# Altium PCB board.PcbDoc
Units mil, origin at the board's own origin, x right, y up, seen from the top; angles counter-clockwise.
Board outline 2598.43 x 1240.16 mil, 2 copper layers (Top Layer, Bottom Layer); 40 components, 36 nets, 194 pads, 31 vias.
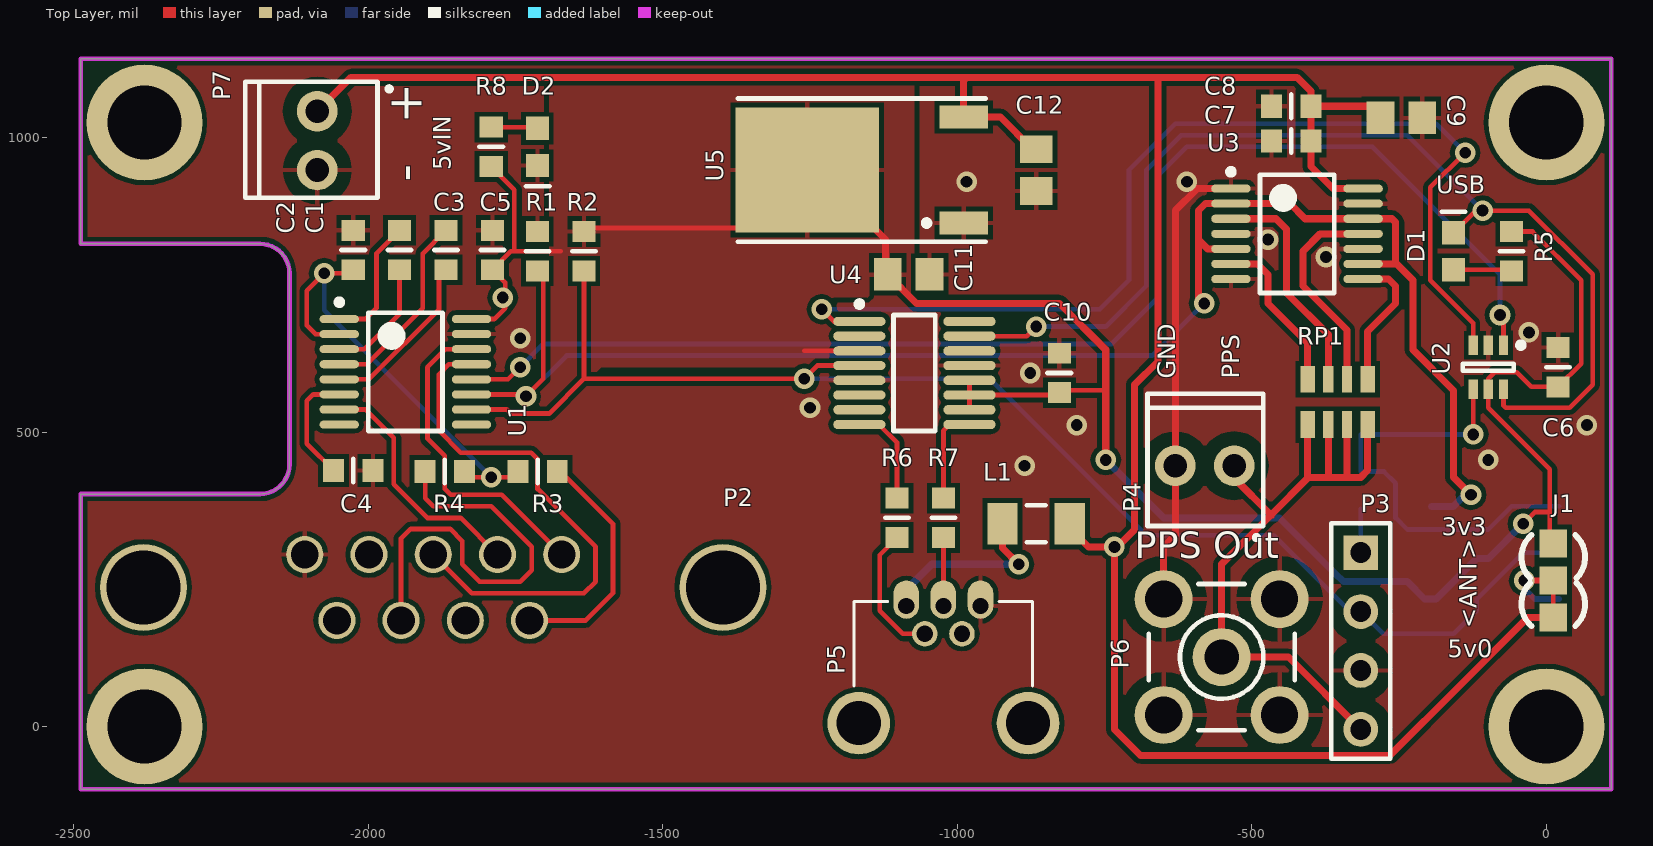
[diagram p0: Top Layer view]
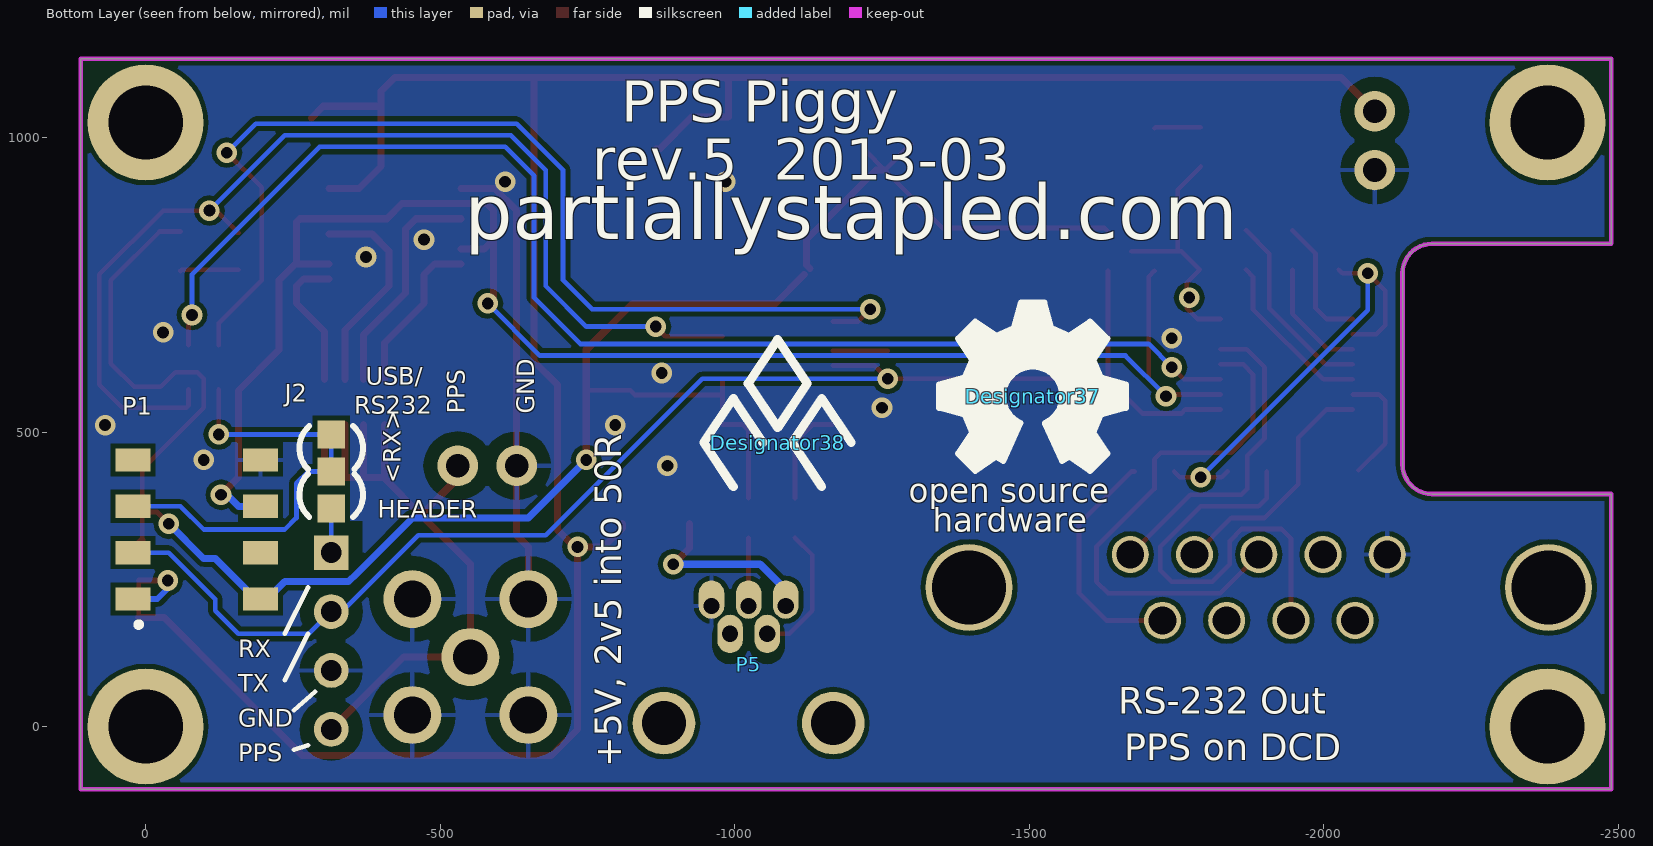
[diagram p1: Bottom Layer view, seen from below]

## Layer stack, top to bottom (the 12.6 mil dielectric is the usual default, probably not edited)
Top Layer: signal copper 1.4
Dielectric: dielectric 12.6, FR-4, Dk 4.8
Bottom Layer: signal copper 1.4

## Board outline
-2488.19,-106.3 -2488.19,394.88 -2183.86,394.88 ccw(c-2183.86,444.88) -2133.86,444.88 -2133.86,769.69 ccw(c-2183.86,769.69) -2183.86,819.69 -2488.19,819.69 -2488.19,1133.86 110.24,1133.86 110.24,-106.3

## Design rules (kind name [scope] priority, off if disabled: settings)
Clearance FarFill [InPolygon vs InComponentClass('FarFill')] p1: gap=23.62
Clearance [All] p2: gap=8
Height [All] p1: minheight=0 maxheight=10000 prefheight=500
HoleSize [All] p1: absolutevalues=TRUE maxlimit=250 minlimit=13 maxpercent=80.000 minpercent=20.000
MinimumAnnularRing [All] p1: minimumring=7
MinimumSolderMaskSliver [All] p1: minsoldermaskwidth=0
NetAntennae jumpers [InNet('VANT') or InNet('RX')] p1: netantennaetolerance=1000
NetAntennae [All] p2: netantennaetolerance=0
PasteMaskExpansion NoPaste [InComponent('U1') or InComponent('U3') or InComponent('U4')] p1: expansion=-100
PasteMaskExpansion [All] p2: expansion=0
PolygonConnect "Direct Vias" [IsVia] p1: connectstyle=Direct reliefconductorwidth=10 reliefentries=4 polygonreliefangle="90 Angle"
PolygonConnect [All] p2: connectstyle=Relief reliefconductorwidth=8 reliefentries=4 polygonreliefangle="90 Angle"
RoutingVias [All] p1: holewidth=20 width=35 viastyle="Through Hole" minholewidth=20 minwidth=35 maxholewidth=20 maxwidth=35
ShortCircuit jumper_rx [InNet('RX') vs InNet('RX_AB')] p1: allowed=TRUE
ShortCircuit jumper_vant [InNet('+5') vs InNet('VANT')] p2: allowed=TRUE
ShortCircuit [All] p3: allowed=FALSE
SilkToSilkClearance [All] p1: silktosilkclearance=1
SilkscreenOverComponentPads [All] p1: minsilkscreentomaskgap=1
SolderMaskExpansion "tent vias" [isvia and (not innet('+3.3') and not innet('gnd'))] p1: expansion=-999
SolderMaskExpansion [All] p2: expansion=4
Width [All] p1: maxlimit=12 minlimit=8 preferedwidth=8
20 further rules are at their usual default settings.

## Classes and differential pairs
component class FarFill: P3 P4 P6 P7

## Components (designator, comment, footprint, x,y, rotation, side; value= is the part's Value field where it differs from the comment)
C1 "100n" RESC1608N -1946.85,809.06 r270 top
C2 "100n" RESC1608N -2025.59,809.06 r270 top
C3 "100n" RESC1608N -1868.11,809.06 r90 top
C4 "100n" RESC1608N -2025.59,435.04 r180 top
C5 "100n" RESC1608N -1789.37,809.06 r270 top
C6 "100n" RESC1608N 19.68,610.24 r270 top
C7 "10n" RESC1608N -433.07,994.09 r0 top
C8 "100n" RESC1608N -433.07,1053.15 r0 top
C9 "10u" RESC2012N -246.06,1033.46 r180 top
C10 "100n" RESC1608N -826.77,600.39 r270 top
C11 "4.7u" RESC2012N -1082.68,767.72 r180 top
C12 "4.7u" RESC2012N -866.14,944.88 r90 top
D1 "GRN" DIO1608N -157.48,807.09 r90 top
D2 "GRN" DIO1608N -1712.6,984.25 r270 top
Designator37 "Comment" OSHW_300 -1505.91,561.02 r180 bottom
Designator38 "Comment" ARMS_250 -1072.83,482.28 r180 bottom
J1 "Solder Jumper" SOL_JUMP_3 11.81,248.03 r270 top
J2 "Solder Jumper" sol_jump_3 -314.96,433.07 r90 bottom
L1 "HI1206T500R-10" RESC3216N -866.14,344.49 r0 top
P1 "To Trimble Board" NPPN042FFKS-RC_REV -47.24,216.54 r90 bottom
P2 "DE-9 Female" DE9_1734348 -1889.76,236.22 r0 top
P3 "Header 4" HDR1X4 -314.96,295.28 r270 top
P4 "640454-2" TEC_640454-2 -629.92,442.91 r0 top
P5 "USB" 0548190519 -1023.62,157.48 r90 top
P6 "SMA" SMA_COAX -551.18,118.11 r0 top
P7 "640454-2" TEC_640454-2 -2086.61,944.88 r90 top
R1 "10K" RESC1608N -1712.6,807.09 r270 top
R2 "10K" RESC1608N -1633.86,807.09 r270 top
R3 "270" RESC1608N -1712.6,433.07 r180 top
R4 "270" RESC1608N -1870.08,433.07 r0 top
R5 "270" RESC1608N -59.06,807.09 r90 top
R6 "22" RESC1608N -1102.36,354.33 r90 top
R7 "22" RESC1608N -1023.62,354.33 r90 top
R8 "270" RESC1608N -1791.34,984.25 r270 top
RP1 "120" CRA06S -354.33,551.18 r0 top
U1 "ST3232CTR" TSSOP16_N -1937.01,602.36 r0 top
U2 "74LVC1G157GW" SOT363-6N -98.43,610.24 r270 top
U3 "SN74ABT125PWLE" PW014_N -423.23,836.61 r0 top
U4 "FT230XS-R" SOP635P600-16N -1072.83,600.39 r0 top
U5 "AP1117D" TO-252 -1122.05,944.88 r90 top

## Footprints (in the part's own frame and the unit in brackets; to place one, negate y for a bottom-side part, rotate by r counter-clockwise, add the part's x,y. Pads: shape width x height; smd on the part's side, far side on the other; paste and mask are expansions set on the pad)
0548190519 [mm] "CONN USB RECEPTACLE 5POS RT ANG"
  round 2.7 hole 1.9: 0(-3.85,-3.65) 0(-3.85,3.65)
  oval 1.65x1.1 hole 0.7 copper offset 0.275,0: 1(1.2,1.6) 3(1.2,0) 5(1.2,-1.6)
  round 1.1 hole 0.7: 2(0,0.8) 4(0,-0.8)
  oval 1.65x1.1 smd far side: 2(0,0.8) 4(0,-0.8)
  silkscreen extent -2.25,-3.85 1.4,3.85, body extent -7.6,-3.85 1.4,3.85, height 3.95
ARMS_250 [mil]
  silkscreen extent -125,-75 125,175
CRA06S [mm]
  rect 0.63x1.15 smd paste-0.05 mask+0: 1(-1.295,0.975) 4(1.295,0.975) 5(1.295,-0.975) 8(-1.295,-0.975)
  rect 0.44x1.15 smd mask+0: 2(-0.4,0.975) 3(0.4,0.975) 6(0.4,-0.975) 7(-0.4,-0.975)
  body extent -1.6,-0.8 1.6,0.8, height 0.5
DE9_1734348 [mm]
  round 3.75 hole 3.2: 0(-12.495,0) 0(12.495,0)
  round 1.6 hole 1.2: 1(5.54,1.42) 2(2.77,1.42) 3(0,1.42) 4(-2.77,1.42) 5(-5.54,1.42) 6(4.155,-1.42) 7(1.385,-1.42) 8(-1.385,-1.42) 9(-4.155,-1.42)
  body extent -15,-9.5 15,3, height 12.5
DIO1608N [mm] "Chip LED, Body 1.6x0.8mm, IPC Medium Density"
  rect 1x1 smd: 1(-0.8,0) 2(0.8,0)
  silkscreen extent 1.7,-0.5 1.7,0.52, body extent -0.87,-0.48 0.87,0.48, height 0.85
HDR1X4 [mm] "Connector; Header; 4 Position"
  rect 1.5x1.5 hole 0.9: 1(0,0)
  round 1.5 hole 0.9: 2(2.54,0) 3(5.08,0) 4(7.62,0)
  silkscreen extent -1.27,-1.27 8.89,1.27
NPPN042FFKS-RC_REV [mm] "2mm header receptacle with bottom entry"
  rect 1x1.5 smd: 1(0,1.75) 2(0,-3.75) 3(2,1.75) 4(2,-3.75) 5(4,1.75) 6(4,-3.75) 7(6,1.75) 8(6,-3.75)
  silkscreen extent -1.2,1.4 -1,1.6, body extent -1,-3 7,1, height 4.4
OSHW_300 [mil]
  silkscreen extent -159,-127 159,159
PW014_N [mm] "TSOP, 14-Leads, Body 5x4.4mm, Pitch 0.65mm, IPC Medium Density"
  oval 1.7x0.35 smd: 1(-2.85,1.95) 2(-2.85,1.3) 3(-2.85,0.65) 4(-2.85,0) 5(-2.85,-0.65) 6(-2.85,-1.3) 7(-2.85,-1.95) 8(2.85,-1.95) 9(2.85,-1.3) 10(2.85,-0.65) 11(2.85,0) 12(2.85,0.65) 13(2.85,1.3) 14(2.85,1.95)
  silkscreen extent -2.97,-2.55 1.6,2.8, body extent -2.25,-2.55 2.25,2.55, height 1.2
RESC1608N [mm] "Chip Resistor, Body 1.6x0.8mm, IPC Medium Density"
  rect 0.9x1 smd: 1(-0.85,0) 2(0.85,0)
  silkscreen extent 0,-0.51 0,0.51, body extent -0.85,-0.48 0.85,0.48, height 0.6
RESC2012N [mm] "Chip Resistor, Body 2.0x1.3mm, IPC Medium Density"
  rect 1.2x1.4 smd: 1(-0.9,0) 2(0.9,0)
  body extent -1.07,-0.7 1.07,0.7, height 0.65
RESC3216N [mm] "Chip Resistor, Body 3.2x1.6mm, IPC Medium Density"
  rect 1.3x1.8 smd: 1(-1.45,0) 2(1.45,0)
  silkscreen extent -0.4,-0.8 0.4,0.8, body extent -1.68,-0.87 1.68,0.87, height 0.71
SMA_COAX [mm] "Connector; SMA Straight"
  round 2.5 hole 1.5: 1(0,0)
  round 2.5 hole 1.6: 2(-2.5,-2.5) 2(-2.5,2.5) 2(2.5,-2.5) 2(2.5,2.5)
  silkscreen extent -3.15,-3.15 3.15,3.15
SOL_JUMP_3 [mm] "3 terminal solder jumper"
  rect 1.2x1.2 smd paste-5.08: 1(-1.6,0) 2(0,0) 3(1.6,0)
  silkscreen extent -1.96,-1.37 1.96,1.37
sol_jump_3 [mm] "3 terminal solder jumper"
  rect 1.2x1.2 smd: 1(-1.6,0) 2(0,0) 3(1.6,0)
  silkscreen extent -1.96,-1.37 1.96,1.37
SOP635P600-16N [mm] "SOP, 16-Leads, Body 4.9x3.9mm, Pitch 0.635mm, IPC Medium Density"
  oval 2.25x0.4 smd: 1(-2.375,2.222) 2(-2.375,1.587) 3(-2.375,0.953) 4(-2.375,0.318) 5(-2.375,-0.317) 6(-2.375,-0.952) 7(-2.375,-1.587) 8(-2.375,-2.222) 9(2.375,-2.222) 10(2.375,-1.587) 11(2.375,-0.952) 12(2.375,-0.317) 13(2.375,0.318) 14(2.375,0.953) 15(2.375,1.587) 16(2.375,2.222)
  silkscreen extent -2.5,-2.5 0.9,3.1, body extent -1.99,-2.5 1.99,2.5, height 1.76
SOT363-6N [mm] "SOT363, 6-Leads, Body 2x1.3mm, Pitch 0.65mm, Lead Span 2.1mm, IPC Medium Density"
  rect 0.85x0.4 smd: 1(-0.95,0.65) 2(-0.95,0) 3(-0.95,-0.65) 4(0.95,-0.65) 5(0.95,0) 6(0.95,0.65)
  silkscreen extent -1.07,-1.1 0.15,1.53, body extent -0.7,-1.1 0.7,1.1, height 1
TEC_640454-2 [mm] "2.54mm pitch header with tab"
  round 1.75 hole 1.02: 1(2.54,0) 2(0,0)
  silkscreen extent -1.2,-3.2 3.8,3.1
TO-252 [mm] "D-PAK/TO-252-AA; 3 Leads (1 Cropped); Body 10.1 (inc. leads) x 6.6 mm (LxW max)"
  rect 1x2.1 smd: 1(-2.285,-3.375) 3(2.285,-3.375)
  rect 5.4x6.2 smd paste-5.08: 4(0,3.375)
  silkscreen extent -3.09,-4.32 3.09,6.38
TSSOP16_N [mm] "TSOP, 16-Leads, Body 5x4.4mm, Pitch 0.65mm, IPC Medium Density"
  oval 1.7x0.35 smd: 1(-2.85,2.275) 2(-2.85,1.625) 3(-2.85,0.975) 4(-2.85,0.325) 5(-2.85,-0.325) 6(-2.85,-0.975) 7(-2.85,-1.625) 8(-2.85,-2.275) 9(2.85,-2.275) 10(2.85,-1.625) 11(2.85,-0.975) 12(2.85,-0.325) 13(2.85,0.325) 14(2.85,0.975) 15(2.85,1.625) 16(2.85,2.275)
  silkscreen extent -2.97,-2.55 1.6,3.12, body extent -2.25,-2.55 2.25,2.55, height 1.1

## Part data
C1 C2 C3 C4 C5 C6 C7 C8 C9 C10 C11 C12: library part Cap, "Capacitor"
D1 D2: library part LED2, "Typical RED, GREEN, YELLOW, AMBER GaAs LED"
J1 J2: library part "Header 3", "Header, 3-Pin"
L1: library part FerriteBead
P1: library part "Header 4X2", "Header, 4-Pin, Dual row"
P2: library part SERIAL_DE9, "DE-9 connector for RS-232"
P3: "Header, 4-Pin"
P4 P7: library part "Header 2", "Header, 2-Pin"
P5: library part "USB OTG", "USB OTG"
P6: library part BNC, "BNC Elbow Connector"
R1 R2 R3 R4 R5 R6 R7 R8: library part Res_G, "Resistor"
RP1: library part ResPack_4
U1: library part MAX3232EEWE, "±15kV ESD-Protected, 3.0V to 5.5V, Low-Power, up to 250kbps, True RS-232 Transceiver"
U3: "Quadruple Bus Buffer Gate with 3-State Outputs"
U5: "Low Dropout Regulator"

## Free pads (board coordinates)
  round 196.85 hole 125.98: 0(-2379.92,0) 0(-2379.92,1025.59) 0(0,0) 0(0,1025.59)
  round 125.98 on Top Paste: 0(-2379.92,0) 0(-2379.92,1025.59) 0(-2379.92,1025.59) 1(-2379.92,0)
  rrect50% 39.37x11.81 on Top Paste: 0(-2057.09,512.8) 0(-1814.96,512.8) 0(-545.28,759.84) 0(-299.21,759.84) 1(-2057.09,538.39) 1(-1814.96,538.39) 1(-545.28,785.43) 1(-299.21,785.43) 2(-2057.09,563.98) 2(-1814.96,563.98) 2(-545.28,811.02) 2(-299.21,811.02) 3(-2057.09,589.57) 3(-1814.96,589.57) 3(-545.28,836.61) 3(-299.21,836.61) 4(-2057.09,615.16) 4(-1814.96,615.16) 4(-545.28,862.2) 4(-299.21,862.2) 5(-2057.09,640.75) 5(-1814.96,640.75) 5(-545.28,887.8) 5(-299.21,887.8) 6(-2057.09,666.34) 6(-1814.96,666.34) 6(-545.28,913.39) 6(-299.21,913.39) 7(-2057.09,691.93) 7(-1814.96,691.93)

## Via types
v1: diameter 35, hole 20, Top Layer to Bottom Layer, 31 vias

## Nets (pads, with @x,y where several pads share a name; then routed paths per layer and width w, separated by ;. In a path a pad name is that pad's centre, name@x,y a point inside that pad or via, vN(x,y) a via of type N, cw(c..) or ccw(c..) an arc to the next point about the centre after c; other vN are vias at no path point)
+3.3: C5.2 C6.2 C10.2 C11.2 J1.1 P1.2 R2.1 R5.2 R8.2 U1.16 U2.5 U4.3 U4.10 U4.11 U4.12 U5.4 | length 3908
  Top Layer w8: U1.16 -1786.42,691.93 -1767.72,710.63 v1@-1767.72,728.35 ; R8.2 -1751.97,911.42 -1751.97,807.09 ; v1(-1771.65,728.35) v1@-1767.72,728.35 ; -1673.23,807.09 -1751.97,807.09 ; R2.1 -1627.95,846.46 -1353.35,846.46 U5.4 ; U5.4@-1299.21,989.17 U5.4 ; -1259.84,637.89 U4.3 ; U5.4@-1220.47,979.33 U5.4 ; U4.10 U4.11 ; U4.12 U4.11 ; -748.03,570.87 -822.83,570.87 C10.2 -830.81,562.89 U4.11 ; R5.2 -23.62,840.55 59.06,757.87 59.06,616.14 C6.2 -25.59,576.77 -50.39,601.57 -87.41,601.57 -98.43,590.55 U2.5 -98.43,541.34 5.91,437.01 5.91,364.17 ; v1(-39.37,344.49) -19.69,364.17 5.91,364.17 ; J1.1@5.91,316.93 5.91,364.17 ; v1@-1767.72,728.35 -1767.72,753.94 C5.2 -1757.87,807.09 -1751.97,807.09
  Top Layer w12: U5.4 -1240.16,944.88 -1122.05,826.77 -1122.05,783.46 C11.2@-1127.95,777.56 ; C11.2 -1118.11,767.6 -1069.01,718.5 -826.77,718.5 -748.03,639.76 -748.03,570.87 v1(-748.03,452.76) ; J1.1@5.91,316.93 J1.1
  Bottom Layer w12: v1(-748.03,452.76) -649.61,354.33 -452.76,354.33 -358.49,260.06 -358.49,259.95 -344.6,246.06 -236.22,246.06 -206.69,216.54 P1.2 -187.01,216.54 -118.11,285.43 -98.43,285.43 v1(-39.37,344.49)
+5: C7.2 C8.2 C9.2 C12.2 J1.3 L1.2 P7.1 U3.14 U5.3 | length 4392
  Top Layer w12: P7.1 -2029.13,1102.36 -1732.28,1102.36 -984.25,1102.36 ; C12.2 -872.05,980.32 -926.57,1034.84 U5.3 -989.17,1097.44 -984.25,1102.36 ; L1.2 -809.06,336.61 -777.56,305.12 v1(-733.27,305.12) ; U3.14 -362.2,913.39 -399.61,950.79 C7.2 C8.2 ; C9.2 -301.18,1053.15 C8.2 ; J1.3 -31.5,185.04 -145.67,70.87 -265.75,-49.21 -688.98,-49.21 -733.27,-4.92 v1(-733.27,305.12) ; -984.25,1102.36 -659.45,1102.36 ; v1(-733.27,305.12) -728.35,305.12 -698.82,334.65 -698.82,580.71 -659.45,620.08 -659.45,1102.36 ; -659.45,1102.36 -423.23,1102.36 -399.61,1078.74 C8.2
GND: C2.1 C4.1 C5.1 C6.1 C7.1 C8.1 C9.1 C10.1 C11.1 C12.1 D2.2 P1.8 P2.5 P3.3 P4.2 P5.5 P6.2 P7.2 R1.1 U1.15 U2.2 U3.1 U3.4 U3.7 U3.10 U3.13 U4.5 U4.13 U5.1 | length 786.3
  Top Layer w12: P6.2@-649.61,216.54 -649.61,305.12 -629.92,324.8 P4.2 -629.92,875.98 -592.52,913.39 U3.1
  Bottom Layer w8: P4.2 P4.2@-623.76,436.76
  other v1: -885.83,442.91 -98.43,452.76 -797.24,511.81 68.9,511.81 -1250,541.34 -875.98,600.39 -1742.13,659.45 -29.53,669.29 -374.02,797.24 -472.44,826.77 -984.25,925.2 -610.24,925.2
NetC1_1: C1.1 U1.1 | length 218.9
  Top Layer w8: U1.1 -2004.92,691.93 -1986.22,710.63 -1986.22,803.15 C1.1
NetC1_2: C1.2 U1.3 | length 202
  Top Layer w8: U1.3 -2006.89,640.75 -1946.85,700.79 C1.2
NetC3_1: C3.1 U1.5 | length 290.4
  Top Layer w8: U1.5 -1999.02,589.57 -1879.92,708.66 -1879.92,763.78 C3.1
NetC3_2: C3.2 U1.4 | length 329.5
  Top Layer w8: U1.4 -2002.95,615.16 -1907.48,710.63 -1907.48,803.15 C3.2
NetD1_1: D1.1 R5.1 | length 99.2
  Top Layer w8: D1.1 -61.02,775.59 R5.1
NetD2_1: D2.1 R8.1 | length 79.6
  Top Layer w8: R8.1 -1714.57,1017.72 D2.1
NetL1_1: L1.1 P5.1 | length 316.8
  Top Layer w12: L1.1 -923.23,303.15 v1(-895.67,275.59)
  Bottom Layer w12: P5.1 -1086.61,232.28 -1043.31,275.59 v1(-895.67,275.59)
NetP2_6: P2.6 R3.1 | length 409.9
  Top Layer w8: P2.6 -1630.71,180.32 -1584.65,226.38 -1584.65,344.49 -1673.23,433.07 R3.1
NetP2_8: P2.8 R4.1 | length 736
  Top Layer w8: P2.8 -1944.29,319.49 -1928.16,335.62 -1861.21,335.62 -1840.55,314.96 -1840.55,275.59 -1811.02,246.06 -1742.13,246.06 -1722.44,265.75 -1722.44,305.12 -1791.34,374.02 -1889.76,374.02 -1903.54,387.8 R4.1
NetR6_2: R6.2 U4.8 | length 171.1
  Top Layer w8: U4.8 -1132.97,512.89 -1102.36,482.28 R6.2
NetR7_2: R7.2 U4.9 | length 163
  Top Layer w8: R7.2 -1023.62,501.97 -1012.7,512.89 U4.9
NetRP1_1: RP1.1 U3.6 | length 276.3
  Top Layer w12: U3.6 -490.16,785.43 -472.44,767.72 -472.44,718.5 -405.32,651.38 RP1.1
NetRP1_2: RP1.2 U3.3 | length 386.1
  Top Layer w12: U3.3 -458.66,862.2 -440.94,844.48 -440.94,736.22 -370.08,665.35 RP1.2
NetRP1_3: RP1.3 U3.11 | length 363.1
  Top Layer w12: RP1.3 -338.58,673.23 -413.39,748.03 -413.39,807.09 -383.86,836.61 U3.11
NetRP1_4: RP1.4 U3.8 | length 238.1
  Top Layer w12: U3.8 -267.72,759.84 -255.91,748.03 -255.91,718.5 -303.35,671.06 RP1.4
PPS: P1.6 R1.2 U1.11 U3.2 U3.5 U3.9 U3.12 | length 2761.9
  Top Layer w8: U1.11 -1735.24,563.98 v1(-1732.28,561.02) -1702.76,590.55 -1702.76,763.78 R1.2
  Top Layer w12: v1(-580.71,718.5) -590.55,728.35 -590.55,826.77 ; U3.5 -574.8,811.02 -590.55,826.77 ; U3.9 -257.87,785.43 -255.91,787.4 ; v1(-127.95,393.7) -157.48,423.23 -157.48,570.87 -226.38,639.76 -226.38,757.87 -255.91,787.4 ; -590.55,826.77 -590.55,875.98 -578.74,887.8 U3.2 -435.04,887.8 -409.45,862.2 U3.12 -261.81,862.2 -255.91,856.3 -255.91,787.4
  Bottom Layer w8: v1(-1732.28,561.02) -1663.39,629.92 -669.29,629.92 v1(-580.71,718.5)
  Bottom Layer w12: P1.6 -157.48,374.02 -137.8,393.7 v1(-127.95,393.7)
PPS_232: P2.1 U1.14 | length 550.9
  Top Layer w8: U1.14 -1869.09,640.75 -1899.61,610.24 -1899.61,489.18 -1870.08,459.66 -1870.08,403.54 -1860.24,393.7 -1773.23,393.7 P2.1
PPS_OUT: P3.4 P4.1 P6.1 RP1.5 RP1.6 RP1.7 RP1.8 | length 1221.9
  Top Layer w12: P4.1 -529.92,421.65 -467.52,359.25 ; RP1.8 -405.32,425 -403.54,423.23 ; RP1.7 -370.08,427.17 -374.02,423.23 ; RP1.6 -338.58,427.17 -334.65,423.23 ; P3.4 -437.8,118.11 P6.1 -551.18,275.59 -468.5,358.27 ; RP1.5 -303.35,434.84 -314.96,423.23 -334.65,423.23 ; -468.5,358.27 -467.52,359.25 ; -468.5,358.27 -466.54,358.27 -467.52,359.25 ; -467.52,359.25 -403.54,423.23 ; -403.54,423.23 -374.02,423.23 ; -374.02,423.23 -334.65,423.23
R+: C2.2 R3.2 R4.2 U1.2 | length 776.3
  Top Layer w8: U1.2 -2089.57,666.34 -2104.33,681.1 -2104.33,740.16 v1(-2074.8,769.69) -2031.5,769.69 C2.2 ; R4.2 -1826.77,423.23 v1(-1791.34,423.23) -1755.91,423.23 R3.2
  Bottom Layer w8: v1(-2074.8,769.69) -2074.8,706.69 v1(-1791.34,423.23)
R-: C4.2 U1.6 | length 196.5
  Top Layer w8: C4.2 -2104.33,480.31 -2104.33,553.15 -2093.5,563.98 U1.6
RX: J2.2 P1.5 | length 491.3
  Bottom Layer w8: -314.96,496.06 J2.2 -275.59,433.07 -255.91,413.39 -255.91,354.33 -236.22,334.65 -98.43,334.65 -59.06,374.02 P1.5
RX_232: P2.3 U1.13 | length 905.4
  Top Layer w8: P2.3 -1824.02,226.38 -1633.86,226.38 -1614.17,246.06 -1614.17,305.12 -1712.6,403.54 -1712.6,453.98 -1723.38,464.76 -1842.71,464.76 -1879.92,501.97 -1879.92,598.43 -1863.19,615.16 U1.13
RX_A: U1.12 U2.1 | length 2242.8
  Top Layer w8: U1.12 -1762.8,589.57 v1(-1742.12,610.23) ; v1(-78.74,698.82) -72.83,692.91 U2.1
  Bottom Layer w8: v1(-1742.12,610.23) -1702.75,649.61 -738.19,649.61 -659.45,728.35 -659.45,935.04 -610.24,984.25 -295.28,984.25 -78.74,767.72 v1(-78.74,698.82)
RX_AB: J2.3 U2.4 | length 267.7
  Top Layer w8: v1(-124.02,496.06) U2.4
  Bottom Layer w8: J2.3 v1(-124.02,496.06)
RX_B: U2.3 U4.1 | length 1806.9
  Top Layer w8: v1(-1230.32,708.66) -1209.55,687.89 U4.1 ; v1(-137.8,974.41) -196.85,915.35 -196.85,757.87 -124.02,685.04 U2.3
  Bottom Layer w8: v1(-1230.32,708.66) -757.87,708.66 -708.66,757.87 -708.66,944.88 -629.92,1023.62 -187.01,1023.62 v1(-137.8,974.41)
RX_C: J2.1 P3.1 | length 74.8
  Bottom Layer w8: P3.1 J2.1
TX: P1.3 P3.2 R2.2 U1.10 U4.4 | length 2407.6
  Top Layer w8: U1.10 -1764.76,538.39 -1757.87,531.5 -1692.91,531.5 -1633.86,590.55 ; R2.2 -1633.86,590.55 ; U4.4 -1237.5,612.89 v1(-1259.84,590.55) -1633.86,590.55
  Bottom Layer w8: v1(-1259.84,590.55) -944.88,590.55 -679.13,324.8 -462.6,324.8 -333.07,195.28 P3.2 -277.17,157.48 -157.48,157.48 -118.11,196.85 -118.11,216.54 -39.37,295.28 P1.3
TX_232: P2.2 U1.7 | length 416.6
  Top Layer w8: U1.7 -2004.92,538.39 -1956.69,490.16 -1956.69,411.42 -1899.61,354.33 -1842.91,354.33 P2.2
USB_ID: P5.4
USB_N: P5.2 R6.1 | length 229.3
  Top Layer w8: R6.1 -1131.89,291.34 -1131.89,196.85 -1092.52,157.48 P5.2@-1055.12,157.48
USB_P: P5.3 R7.1 | length 116.1
  Top Layer w8: P5.3 R7.1
USBCFG: D1.2 U2.6 U4.15 | length 1863.2
  Top Layer w8: U4.15 -882.38,662.89 v1(-866.14,679.13) ; D1.2@-155.51,838.58 D1.2 -120.08,875.98 v1(-108.27,875.98) -29.53,875.98 78.74,767.72 78.74,580.71 39.37,541.34 -68.9,541.34 -72.83,545.28 U2.6
  Bottom Layer w8: v1(-866.14,679.13) -748.03,679.13 -679.13,748.03 -679.13,944.88 -620.08,1003.94 -236.22,1003.94 v1(-108.27,875.98)
VANT: J1.2 P1.1 | length 194
  Top Layer w8: 11.81,185.04 J1.2
  Top Layer w10: v1(-37.4,248.03) J1.2
  Bottom Layer w10: v1(-37.4,248.03) -39.37,246.06 -39.37,236.22 -19.69,216.54 P1.1
pads on no net: P1.4 P1.7 P2.0 P2.4 P2.7 P2.9 P5.0 U1.8 U1.9 U4.2 U4.6 U4.7 U4.14 U4.16

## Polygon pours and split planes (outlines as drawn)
+3.3 on Top Layer "fill" (solid, remove dead copper, pour order 4): -1692.91,1102.36 -1072.83,1102.36 -1072.83,728.35 -1210.63,728.35 -1210.63,610.24 -1604.33,610.24 -1732.28,482.28 -1732.28,629.92 -1692.91,669.29
GND on Top Layer "topgnd" (solid, remove dead copper, pour order 4): -2527.56,1133.86 -2527.56,-106.3 110.24,-106.3 110.24,1133.86
GND on Bottom Layer "topgnd" (solid, remove dead copper, pour order 6): -2527.56,-106.3 -2527.56,1133.86 110.24,1133.86 110.24,-106.3

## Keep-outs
Keep-Out Layer:
  the board outline again, w7.87

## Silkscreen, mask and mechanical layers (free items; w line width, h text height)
Top Overlay:
  text "+" at -1909.45,1023.62 h60 r90
  text "5vIN" at -1860.24,944.88 h30 r90
  text "-" at -1909.45,925.2 h60 r90
  text "USB" at -187.01,905.51 h30
  text "GND" at -629.92,590.55 h30 r90
  text "PPS" at -521.65,590.55 h30 r90
  text "3v3" at -177.17,324.8 h30
  text "PPS Out" at -698.82,285.43 h45
  text "<ANT>" at -118.11,167.32 h30 r90
  text "5v0" at -167.32,118.11 h30
Bottom Overlay:
  lines w8: -287.4,59.06 -251.97,27.56 ; -275.59,-31.5 -251.97,-39.37 ; -275.59,157.48 -236.22,78.74 ; -275.59,236.22 -236.22,157.48
  text "PPS Piggy" at -807.09,1003.94 h120
  text "rev.5  2013-03" at -757.87,905.51 h120
  text "partiallystapled.com" at -541.34,797.24 h160
  text "USB/" at -374.02,580.71 h30
  text "GND" at -659.45,531.5 h30 r270
  text "PPS" at -541.34,531.5 h30 r270
  text "RS232" at -354.33,531.5 h30
  text "<RX>" at -433.07,413.39 h30 r270
  text "HEADER" at -393.7,354.33 h30
  text "RX" at -157.48,118.11 h30
  text "TX" at -157.48,59.06 h30
  text "RS-232 Out" at -1651.57,21.65 h45
  text "GND" at -157.48,0 h30
  text "PPS on DCD" at -1661.42,-57.09 h45
  text "PPS" at -157.48,-59.06 h30
  text "+5V, 2v5 into 50R" at -807.09,-68.9 h45 r270
Top Paste:
  region: -1240.16,1033.46 -1240.16,954.72 -1141.73,954.72 -1141.73,1033.46
  region: -1141.73,856.3 -1141.73,935.04 -1240.16,935.04 -1240.16,856.3
  region: -1368.11,1033.46 -1368.11,954.72 -1269.69,954.72 -1269.69,1033.46
  region: -1269.69,856.3 -1269.69,935.04 -1368.11,935.04 -1368.11,856.3
Top Solder:
  lines w12: 11.81,188.98 11.81,314.96
Bottom Solder:
  lines w12: -314.96,366.14 -314.96,496.06
Mechanical 5:
  lines w10: -2480.32,-118.11 -2480.32,1141.73 118.11,1141.73 118.11,-118.11 -2480.32,-118.11
Mechanical 15:
  lines w3.94: -2409.45,819.68 ccw(c-2409.45,819.69) -2409.45,819.69

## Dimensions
0,0 to 0,1025.59 on Mechanical 1
0,1025.59 to -2379.92,1025.59 on Mechanical 1
110.24,1133.86 to 110.24,-106.3 on Mechanical 1
-2488.19,1133.86 to 110.24,1133.86 on Mechanical 1
-2488.19,1133.86 to 110.24,1133.86 on Mechanical 1
110.24,-106.3 to 110.24,1133.86 on Mechanical 1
